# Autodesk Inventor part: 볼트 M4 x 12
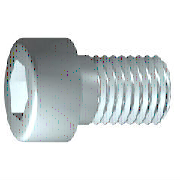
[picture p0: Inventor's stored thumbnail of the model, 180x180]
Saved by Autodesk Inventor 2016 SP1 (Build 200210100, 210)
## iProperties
IsCustomPart: 0
Created: 2012-02
Part Number: 볼트 M4 x 12
Material: 강철, 연강
Description: 6각 소켓 머리 캡 나사
Document SubType Name: Modeling
Standard: ISO 4762
Designer: mduedu
Standard Revision: Fourth edition 2004-03-01
Standards Organization: ISO
Language: ko-KR
Size Designation: M4 x 12
Categories: <MemberInstance><Categories><Category DisplayName="조임쇠" InternalName="e4da775c-781d-43d5-af7c-5136215cf5a6" Mnemonic="FSTN"><Category DisplayName="볼트" InternalN
Density: 7.75 g/cm^3
Appearance: 강철
Author: mduedu
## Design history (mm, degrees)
sketch "스케치1"
  geometry: L1 (-1, 0)-(12, 0); L2 (12, 0)-(12, 2); L3 (12, 2)-(1.75, 2); L4 (1.75, 2)-(1.32, 2); L5 (1.32, 2)-(0, 2); L6 (0, 2)-(0, 3.5); L7 (0, 3.5)-(-4, 3.5); L8 (-4, 3.5)-(-4, 1.732); L9 (-4, 1.732)-(-2, 1.732); L10 (-2, 1.732)-(-1, 0); L11 (-7.2, 0)-(15.2, 0) reference; L12 (0, -0.7)-(0, 4.2) reference; L13 (1.75, 2)-(0, 2)
  constraints: 22 end point, 6 parallel, 2 collinear, 2 perpendicular, 1 horizontal, 1 point on line
  dimensions: "d1" = 10.25 distance from line of L3.end L2 (= GEL); "d2" = 0.42952 distance of L4.end L3.end (computed from GAL); "d3" = 4 distance between parallel lines of L8 L6 (= KOH); "d4" = 2 distance of L8.end L9.end (= INTI); "d5" = 60 deg angle of L10 L1; "d6" = 4 diameter of L3 L1 (= GD); "d7" = 4 diameter of L5 L1 (= BDM); "d8" = 3.4641 diameter of L9 L1 (= 1.1547 x SW); "d9" = 7 diameter of L7 L1 (= KOD); "d26" = 12 distance between parallel lines of L12 L2 (= NLG)
revolve "본체" sketch "스케치1" stored, may be unused: angle "d10" = 90 deg
sketch "스케치2"
  geometry: L1 (0, -4.9)-(0, 4.9) reference; L2 (-4.9, 0)-(4.9, 0) reference; L3 (1.732, 0)-(0.866, -1.5); L4 (0.866, -1.5)-(-0.866, -1.5); L5 (-0.866, -1.5)-(-1.732, 0); L6 (-1.732, 0)-(-0.866, 1.5); L7 (-0.866, 1.5)-(0.866, 1.5); L8 (0.866, 1.5)-(1.732, 0); 2 further points
  constraints: 12 end point, 1 coincident, 1 horizontal alignment, 1 point on line, 12 other
extrude "슬롯" join sketch "스케치2" stored distance "d11" = 10; taper "d12" = 0 deg
workplane "Work Plane1"
fillet "Fillet2" dims "d30" = 0.1 (= R)
body "Solid1"
fillet "모깎기1" dims "d17" = 0.4 (= RR)
feature "스레드" dims "d13" = 10.25 (= GEL), "d14" = 0
chamfer "모따기1" distance "d15" = 0.42941 (= -0.5 x SPD + 0.5 x GD); stored, may be unused: second distance "d16" = 0.42941 (= GUL), angle "d27" = 45 deg
other parameters: "GD" = 4 [user parameter; used in 2 equation terms], "NLG" = 12 [user parameter; used in 1 equation term], "GEL" = 10.25 [user parameter; used in 2 equation terms], "KOD" = 7 [user parameter; used in 1 equation term], "KOH" = 4 [user parameter; used in 1 equation term], "INTI" = 2 [user parameter; used in 1 equation term], "GAL" = 0.42941 (= 0.61345 x PTC) [user parameter; used in 1 equation term], "GUL" = 0.42941 (= 0.61345 x PTC) [user parameter; used in 1 equation term], "BDM" = 4 (= NND) [user parameter; used in 1 equation term], "SW" = 3 [user parameter; used in 2 equation terms], "RR" = 0.4 [user parameter; used in 1 equation term], "SPD" = 3.14117 (= NND - 1.2269 x PTC) [user parameter; used in 1 equation term], "d19" = 0, "d28" = 0, "d29" = 0, "R" = 0.1 [user parameter; used in 1 equation term], "TOA" = 30 deg [user parameter], "GD1" = 3.14117 (= THREADDIA - 1.2269 x PTC) [user parameter], "THREADDIA" = 4 [user parameter; used in 1 equation term], "FAWI" = 45 deg [user parameter], "TPU" = 14.28571 (computed from PTC) [user parameter], "PTC" = 0.7 [user parameter; used in 5 equation terms], "NND" = 4 [user parameter; used in 2 equation terms], "E0" = 3.465 (= 1.155 x SW) [user parameter]
